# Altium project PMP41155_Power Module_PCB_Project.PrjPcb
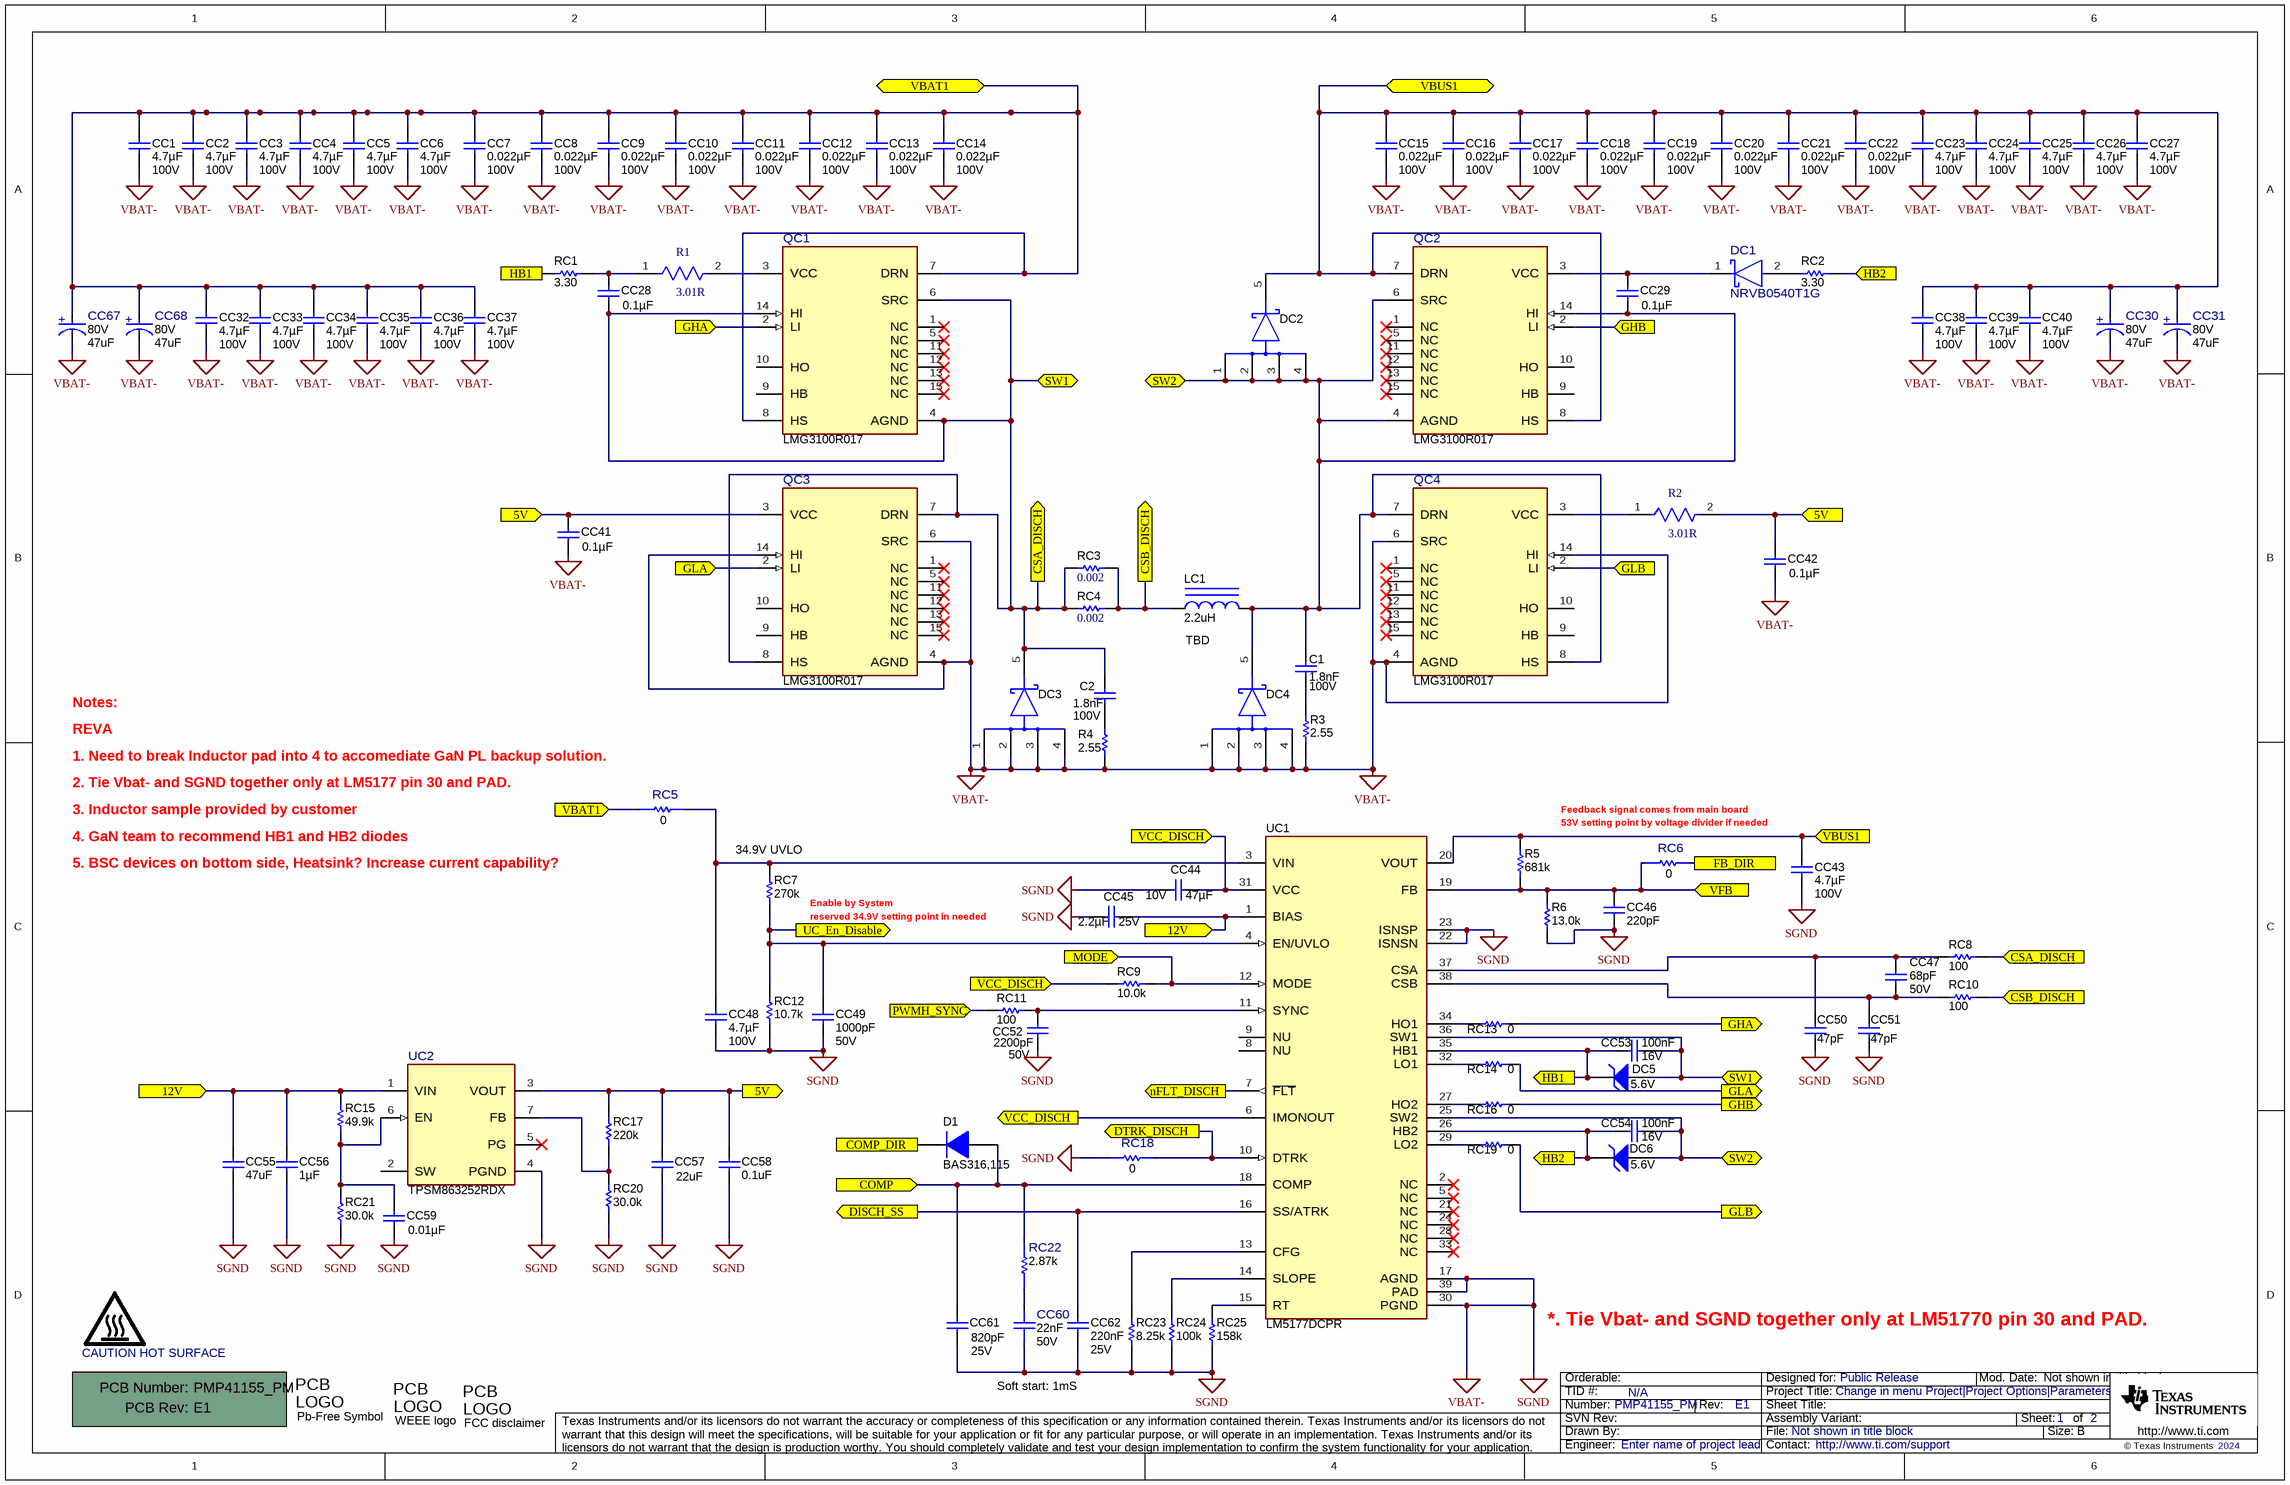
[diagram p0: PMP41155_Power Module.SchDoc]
CopyrightYear: 2024; PCB_Layout: Richard Yin; PCB_Rev: E1; PRJ_Customer: Public Release; PRJ_Engineer: Enter name of project lead; PRJ_Number: PMP41155_PM; PRJ_Title: Change in menu Project|Project Options|Parameters; SCH_Rev: E1; TechSupport: http://www.ti.com/support; TID: N/A
2 sheets, 131 parts. Net scope: flat (ports and power ports of the same name join across sheets).
Board file: PMP41155_Power Module.PcbDoc
Sheets:
  PMP41155_Power Module.SchDoc
  PMP41155_Power Module_1.SchDoc

## Sheet PMP41155_Power Module.SchDoc
size 431 x 279 mm; Date: Not shown in title block; ApprovedBy: Not shown in title block; CheckedBy: Not shown in title block; Author: Not shown in title block; CompanyName: Not shown in title block; Engineer: Not shown in title block; Organization: Not shown in title block; Address1: Not shown in title block; Address2: Not shown in title block; Address3: Not shown in title block; Address4: Not shown in title block; DocumentNumber: 1; Revision: Use project parameter SCH_Rev; SheetNumber: 1; SheetTotal: 2; PageSetup: Record=PageOptions¦CenterHorizontal=True¦CenterVertical=True¦PrintScale=1.00¦XCorrection=1.00¦YCorrection=1.00¦PrintKind=0¦BorderSize=5000000¦LeftOffset=0¦BottomOffset=0¦Orientation=2¦PaperLength=1000¦PaperWidth=1000¦Scale=100¦PaperSource=15¦PrintQuality=600¦MediaType=1¦DitherType=10¦PaperKind=Letter¦PrintScaleMode=1

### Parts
!PCB1  Printed Circuit Board  (value not drawn)  (mechanical)
C1  Cap_F: 1.8nF  VDC_V: 100V  [0603]  (hidden comment: GRM188R72A182KA01D)
C2  Cap_F: 1.8nF  VDC_V: 100V  [0603]  (hidden comment: GRM188R72A182KA01D)
CC1  ValueDisplayed: 4.7µF  Value2: 100V  [1206_180]  (hidden comment: GRJ31CC72A475KE01L)
CC2  ValueDisplayed: 4.7µF  Value2: 100V  [1206_180]  (hidden comment: GRJ31CC72A475KE01L)
CC3  ValueDisplayed: 4.7µF  Value2: 100V  [1206_180]  (hidden comment: GRJ31CC72A475KE01L)
CC4  ValueDisplayed: 4.7µF  Value2: 100V  [1206_180]  (hidden comment: GRJ31CC72A475KE01L)
CC5  ValueDisplayed: 4.7µF  Value2: 100V  [1206_180]  (hidden comment: GRJ31CC72A475KE01L)
CC6  ValueDisplayed: 4.7µF  Value2: 100V  [1206_180]  (hidden comment: GRJ31CC72A475KE01L)
CC7  ValueDisplayed: 0.022µF  Value2: 100V  [0603]  (hidden comment: CGA3E2X7R2A223K080AA)
CC8  ValueDisplayed: 0.022µF  Value2: 100V  [0603]  (hidden comment: CGA3E2X7R2A223K080AA)
CC9  ValueDisplayed: 0.022µF  Value2: 100V  [0603]  (hidden comment: CGA3E2X7R2A223K080AA)
CC10  ValueDisplayed: 0.022µF  Value2: 100V  [0603]  (hidden comment: CGA3E2X7R2A223K080AA)
CC11  ValueDisplayed: 0.022µF  Value2: 100V  [0603]  (hidden comment: CGA3E2X7R2A223K080AA)
CC12  ValueDisplayed: 0.022µF  Value2: 100V  [0603]  (hidden comment: CGA3E2X7R2A223K080AA)
CC13  ValueDisplayed: 0.022µF  Value2: 100V  [0603]  (hidden comment: CGA3E2X7R2A223K080AA)
CC14  ValueDisplayed: 0.022µF  Value2: 100V  [0603]  (hidden comment: CGA3E2X7R2A223K080AA)
CC15  ValueDisplayed: 0.022µF  Value2: 100V  [0603]  (hidden comment: CGA3E2X7R2A223K080AA)
CC16  ValueDisplayed: 0.022µF  Value2: 100V  [0603]  (hidden comment: CGA3E2X7R2A223K080AA)
CC17  ValueDisplayed: 0.022µF  Value2: 100V  [0603]  (hidden comment: CGA3E2X7R2A223K080AA)
CC18  ValueDisplayed: 0.022µF  Value2: 100V  [0603]  (hidden comment: CGA3E2X7R2A223K080AA)
CC19  ValueDisplayed: 0.022µF  Value2: 100V  [0603]  (hidden comment: CGA3E2X7R2A223K080AA)
CC20  ValueDisplayed: 0.022µF  Value2: 100V  [0603]  (hidden comment: CGA3E2X7R2A223K080AA)
CC21  ValueDisplayed: 0.022µF  Value2: 100V  [0603]  (hidden comment: CGA3E2X7R2A223K080AA)
CC22  ValueDisplayed: 0.022µF  Value2: 100V  [0603]  (hidden comment: CGA3E2X7R2A223K080AA)
CC23  ValueDisplayed: 4.7µF  Value2: 100V  [1206_180]  (hidden comment: GRJ31CC72A475KE01L)
CC24  ValueDisplayed: 4.7µF  Value2: 100V  [1206_180]  (hidden comment: GRJ31CC72A475KE01L)
CC25  ValueDisplayed: 4.7µF  Value2: 100V  [1206_180]  (hidden comment: GRJ31CC72A475KE01L)
CC26  ValueDisplayed: 4.7µF  Value2: 100V  [1206_180]  (hidden comment: GRJ31CC72A475KE01L)
CC27  ValueDisplayed: 4.7µF  Value2: 100V  [1206_180]  (hidden comment: GRJ31CC72A475KE01L)
CC28  ValueDisplayed: 0.1µF  [0402]  (hidden comment: GCM155R71C104JA55D)
CC29  ValueDisplayed: 0.1µF  [0402]  (hidden comment: GCM155R71C104JA55D)
CC30  VDC_V: 80V  ValueDisplayed: 47uF  [FP-865081757008_SMT_CAP_10MM3_10MM3-MFG]  (hidden comment: 865081757008)
CC31  VDC_V: 80V  ValueDisplayed: 47uF  [FP-865081757008_SMT_CAP_10MM3_10MM3-MFG]  (hidden comment: 865081757008)
CC32  ValueDisplayed: 4.7µF  Value2: 100V  [1206_180]  (hidden comment: GRJ31CC72A475KE01L)
CC33  ValueDisplayed: 4.7µF  Value2: 100V  [1206_180]  (hidden comment: GRJ31CC72A475KE01L)
CC34  ValueDisplayed: 4.7µF  Value2: 100V  [1206_180]  (hidden comment: GRJ31CC72A475KE01L)
CC35  ValueDisplayed: 4.7µF  Value2: 100V  [1206_180]  (hidden comment: GRJ31CC72A475KE01L)
CC36  ValueDisplayed: 4.7µF  Value2: 100V  [1206_180]  (hidden comment: GRJ31CC72A475KE01L)
CC37  ValueDisplayed: 4.7µF  Value2: 100V  [1206_180]  (hidden comment: GRJ31CC72A475KE01L)
CC38  ValueDisplayed: 4.7µF  Value2: 100V  [1206_180]  (hidden comment: GRJ31CC72A475KE01L)
CC39  ValueDisplayed: 4.7µF  Value2: 100V  [1206_180]  (hidden comment: GRJ31CC72A475KE01L)
CC40  ValueDisplayed: 4.7µF  Value2: 100V  [1206_180]  (hidden comment: GRJ31CC72A475KE01L)
CC41  ValueDisplayed: 0.1µF  [0402]  (hidden comment: GCM155R71C104JA55D)
CC42  ValueDisplayed: 0.1µF  [0402]  (hidden comment: GCM155R71C104JA55D)
CC43  ValueDisplayed: 4.7µF  Value2: 100V  [1206_180]  (hidden comment: GRJ31CC72A475KE01L)
CC44  VDC_V: 10V  ValueDisplayed: 47µF  [0805_HV]  (hidden comment: GRM21BR61A476ME15L)
CC45  ValueDisplayed: 2.2µF  Value2: 25V  [0805_HV]  (hidden comment: GRM219R61E225KA12D)
CC46  ValueDisplayed: 220pF  [0603]  (hidden comment: GRM188R71H221KA01D)
CC47  ValueDisplayed: 68pF  Value2: 50V  [0603]  (hidden comment: 06035A680JAT2A)
CC48  ValueDisplayed: 4.7µF  Value2: 100V  [1206_180]  (hidden comment: GRJ31CC72A475KE01L)
CC49  ValueDisplayed: 1000pF  Value2: 50V  [0603]  (hidden comment: GRM1885C1H102JA01D)
CC50  ValueDisplayed: 47pF  [0603]  (hidden comment: C0603C470J5GACTU)
CC51  ValueDisplayed: 47pF  [0603]  (hidden comment: C0603C470J5GACTU)
CC52  ValueDisplayed: 2200pF  Value2: 50V  [0603]  (hidden comment: GRM188R61H222KA01D)
CC53  Cap_F: 100nF  VDC_V: 16V  [0603]  (hidden comment: GCM188R71C104KA37J)
CC54  Cap_F: 100nF  VDC_V: 16V  [0603]  (hidden comment: GCM188R71C104KA37J)
CC55  ValueDisplayed: 47uF  [1210_270]  (hidden comment: GRM32ER61C476KE15L)
CC56  Cap_F: 1µF  [0805_HV]  (hidden comment: C0805C105K3RACTU)
CC57  ValueDisplayed: 22uF  [0805_HV]  (hidden comment: CL21A226KQQNNNE)
CC58  ValueDisplayed: 0.1uF  [0402]  (hidden comment: GRM155R70J104KA01D)
CC59  ValueDisplayed: 0.01µF  [0402]  (hidden comment: C0402C103K4RACTU)
CC60  Cap_F: 22nF  VDC_V: 50V  [FP-CL10B223KB8NNNC_0603-IPC_C]  (hidden comment: CL10B223KB8NNNC)
CC61  VDC_V: 25V  ValueDisplayed: 820pF  [0603]  (hidden comment: GRM1885C1E821JA01D)
CC62  Cap_F: 220nF  VDC_V: 25V  [0805_HV]  (hidden comment: 08053C224MAT2A)
CC67  VDC_V: 80V  ValueDisplayed: 47uF  [FP-865081757008_SMT_CAP_10MM3_10MM3-MFG]  (hidden comment: 865081757008)
CC68  VDC_V: 80V  ValueDisplayed: 47uF  [FP-865081757008_SMT_CAP_10MM3_10MM3-MFG]  (hidden comment: 865081757008)
D1  BAS316,115  [SOD-323]
DC1  NRVB0540T1G  [FP-NRVB0540T1G_SOD-123-MFG]
DC2  STPS30M100DJF-TR  [FP-STPS30M100DJF-TR_PowerFlat6-MFG]  (value not drawn)
DC3  STPS30M100DJF-TR  [FP-STPS30M100DJF-TR_PowerFlat6-MFG]  (value not drawn)
DC4  STPS30M100DJF-TR  [FP-STPS30M100DJF-TR_PowerFlat6-MFG]  (value not drawn)
DC5  value 5.6V  [SOD-123]  (hidden comment: MMSZ4690-E3-08)
DC6  value 5.6V  [SOD-123]  (hidden comment: MMSZ4690-E3-08)
LC1  TBD  ValueDisplayed: 2.2uH  [WE-HCB_1890]
LOGO1  CAUTION HOT SURFACE  [IEC_HotSurface_Small]  (no BOM)
Logo2  Pb-Free Symbol  [Pb-Free_Overlay_Medium]  (no BOM)
Logo3  WEEE logo  [WEEE_Minimum]  (no BOM)
Logo4  FCC disclaimer  [FCC_disclaimer]  (no BOM)
QC1  LMG3100R017  [VBE0015A-MFG]
QC2  LMG3100R017  [VBE0015A-MFG]
QC3  LMG3100R017  [VBE0015A-MFG]
QC4  LMG3100R017  [VBE0015A-MFG]
R1  Resistance: 3.01R  [FP-CRCW0402-e3-MFG]  (hidden comment: CRCW04023R01FNED)
R2  Resistance: 3.01R  [FP-CRCW0402-e3-MFG]  (hidden comment: CRCW04023R01FNED)
R3  ValueDisplayed: 2.55  [1206]  (hidden comment: CRCW12062R55FKEA)
R4  ValueDisplayed: 2.55  [1206]  (hidden comment: CRCW12062R55FKEA)
R5  ValueDisplayed: 681k  [0603]  (hidden comment: CRCW0603681KFKEA)
R6  ValueDisplayed: 13.0k  [0603]  (hidden comment: CRCW060313K0FKEA)
RC1  ValueDisplayed: 3.30  [1206]  (hidden comment: RC1206FR-073R3L)
RC2  ValueDisplayed: 3.30  [1206]  (hidden comment: RC1206FR-073R3L)
RC3  ValueDisplayed: 0.002  [0508]  (hidden comment: KRL2012E-M-R002-G-T5)
RC4  ValueDisplayed: 0.002  [0508]  (hidden comment: KRL2012E-M-R002-G-T5)
RC5  Res_ohm: 0  [FP-JR0805X35E_0805-MFG]  (hidden comment: JR0805X35E)
RC6  Res_ohm: 0  [FP-JR0805X35E_0805-MFG]  (hidden comment: JR0805X35E)
RC7  ValueDisplayed: 270k  [0603]  (hidden comment: CRCW0603270KJNEA)
RC8  ValueDisplayed: 100  [0603]  (hidden comment: RC0603FR-07100RL)
RC9  ValueDisplayed: 10.0k  [0603]  (hidden comment: CRCW060310K0FKEA)
RC10  ValueDisplayed: 100  [0603]  (hidden comment: RC0603FR-07100RL)
RC11  ValueDisplayed: 100  [0603]  (hidden comment: CRCW0603100RFKEA)
RC12  ValueDisplayed: 10.7k  [0603]  (hidden comment: CRCW060310K7FKEA)
RC13  ValueDisplayed: 0  [0603]  (hidden comment: CRCW06030000Z0EA)
RC14  ValueDisplayed: 0  [0603]  (hidden comment: CRCW06030000Z0EA)
RC15  ValueDisplayed: 49.9k  [0402]  (hidden comment: CRCW040249K9FKED)
RC16  ValueDisplayed: 0  [0603]  (hidden comment: CRCW06030000Z0EA)
RC17  ValueDisplayed: 220k  [0402]  (hidden comment: RC0402FR-07220KL)
RC18  Res_ohm: 0  [FP-JR0805X35E_0805-MFG]  (hidden comment: JR0805X35E)
RC19  ValueDisplayed: 0  [0603]  (hidden comment: CRCW06030000Z0EA)
RC20  ValueDisplayed: 30.0k  [0402]  (hidden comment: CRCW040230K0FKED)
RC21  ValueDisplayed: 30.0k  [0402]  (hidden comment: CRCW040230K0FKED)
RC22  Res_ohm: 2.87k  [FP-RK73H1ETTP2871F_0402-MFG]  (hidden comment: RK73H1ETTP2871F)
RC23  ValueDisplayed: 8.25k  [0603]  (hidden comment: CRCW06038K25FKEA)
RC24  ValueDisplayed: 100k  [0603]  (hidden comment: CRCW0603100KFKEA)
RC25  ValueDisplayed: 158k  [0603]  (hidden comment: CRCW0603158KFKEA)
UC1  LM5177DCPR  [DCP0038A-MFG]
UC2  TPSM863252RDX  [RDX0007A-MFG]

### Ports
5V (in), 5V (out), 12V (in), COMP (in), COMP_DIR (out), CSA_DISCH (in), CSA_DISCH (out), CSB_DISCH (in), CSB_DISCH (out), DISCH_SS (out), DTRK_DISCH (out), FB_DIR (in), GHA (in), GHA (out), GHB (in), GHB (out), GLA (in), GLA (out), GLB (in), GLB (out), HB1 (in), HB1 (out), HB2 (in), HB2 (out), MODE (in), nFLT_DISCH (out), PWMH_SYNC (in), SW1 (bidir), SW2 (bidir), UC_En_Disable (out), VBAT1 (bidir), VBAT1 (in), VBUS1 (bidir), VBUS1 (in), VCC_DISCH (in), VCC_DISCH (out), VFB (in)

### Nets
SGND: CC1.2 CC2.2 CC3.2 CC4.2 CC5.2 CC6.2 CC7.2 CC8.2 CC9.2 CC10.2 CC11.2 CC12.2 CC13.2 CC14.2 CC15.2 CC16.2 CC17.2 CC18.2 CC19.2 CC20.2 CC21.2 CC22.2 CC23.2 CC24.2 CC25.2 CC26.2 CC27.2 CC30.1(CATHODE) CC31.1(CATHODE) CC32.2 CC33.2 CC34.2 CC35.2 CC36.2 CC37.2 CC38.2 CC39.2 CC40.2 CC41.2 CC42.2 CC43.2 CC44.2 CC45.1 CC46.2 CC48.2 CC49.2 CC50.2 CC51.2 CC52.1 CC55.2 CC56.2 CC57.2 CC58.2 CC59.2 CC60.1 CC61.2 CC62.2 CC67.1(CATHODE) CC68.1(CATHODE) DC3.1(A) DC3.2(A) DC3.3(A) DC3.4(A) DC4.1(A) DC4.2(A) DC4.3(A) DC4.4(A) QC3.4(AGND) QC3.6(SRC) QC3.14(HI) QC4.4(AGND) QC4.6(SRC) QC4.14(HI) R3.1 R4.1 R6.1 RC12.1 RC18.1 RC20.1 RC21.1 RC23.1 RC24.1 RC25.1 UC1.17(AGND) UC1.22(ISNSN) UC1.23(ISNSP) UC1.30(PGND) UC1.39(PAD) UC2.4(PGND)  [also labelled VBAT-]
5V: CC41.1 CC42.1 CC57.1 CC58.1 QC3.3(VCC) R2.2 RC17.2 UC2.3(VOUT) ; port 5V
12V: CC45.2 CC55.1 CC56.1 RC15.2 UC1.1(BIAS) UC2.1(VIN) ; port 12V
COMP: CC61.1 D1.2(A) RC22.2 UC1.18(COMP) ; port COMP
COMP_DIR: D1.1(K) ; port COMP_DIR
CSA_DISCH: C2.1 CC28.2 CC53.1 DC3.5(K) DC5.2(A) QC1.4(AGND) QC1.6(SRC) QC1.14(HI) QC3.7(DRN) QC3.8(HS) RC3.1 RC4.1 RC8.2 UC1.36(SW1) ; port CSA_DISCH, port SW1
CSB_DISCH: LC1.1 RC3.2 RC4.2 RC10.2 ; port CSB_DISCH
DISCH_SS: CC62.1 UC1.16(SS/ATRK) ; port DISCH_SS
DTRK_DISCH: RC18.2 UC1.10(DTRK) ; port DTRK_DISCH
FB_DIR: RC6.2 ; port FB_DIR
GHA: QC1.2(LI) RC13.2 ; port GHA
GHB: QC2.2(LI) RC16.2 ; port GHB
GLA: QC3.2(LI) RC14.2 ; port GLA
GLB: QC4.2(LI) RC19.2 ; port GLB
HB1: CC53.2 DC5.1(K) RC1.1 UC1.35(HB1) ; port HB1
HB2: CC54.2 DC6.1(K) RC2.2 UC1.26(HB2) ; port HB2
MODE: RC9.2 UC1.12(MODE) ; port MODE
nFLT_DISCH: UC1.7(~{FLT}) ; port nFLT_DISCH
PWMH_SYNC: RC11.1 ; port PWMH_SYNC
SW2: C1.1 CC29.2 CC54.1 DC2.1(A) DC2.2(A) DC2.3(A) DC2.4(A) DC4.5(K) DC6.2(A) LC1.2 QC2.4(AGND) QC2.6(SRC) QC2.14(HI) QC4.7(DRN) QC4.8(HS) UC1.25(SW2) ; port SW2
UC_En_Disable: CC49.1 RC7.1 RC12.2 UC1.4(EN/UVLO) ; port UC_En_Disable
VBAT1: CC1.1 CC2.1 CC3.1 CC4.1 CC5.1 CC6.1 CC7.1 CC8.1 CC9.1 CC10.1 CC11.1 CC12.1 CC13.1 CC14.1 CC32.1 CC33.1 CC34.1 CC35.1 CC36.1 CC37.1 CC67.2(ANODE) CC68.2(ANODE) QC1.7(DRN) QC1.8(HS) RC5.1 ; port VBAT1
VBUS1: CC15.1 CC16.1 CC17.1 CC18.1 CC19.1 CC20.1 CC21.1 CC22.1 CC23.1 CC24.1 CC25.1 CC26.1 CC27.1 CC30.2(ANODE) CC31.2(ANODE) CC38.1 CC39.1 CC40.1 CC43.1 DC2.5(K) QC2.7(DRN) QC2.8(HS) R5.2 UC1.20(VOUT) ; port VBUS1
VCC_DISCH: CC44.1 RC9.1 UC1.6(IMONOUT) UC1.31(VCC) ; port VCC_DISCH
VFB: CC46.1 R5.1 R6.2 RC6.1 UC1.19(FB) ; port VFB
NetC1_2: C1.2 R3.2
NetC2_2: C2.2 R4.2
NetCC28_1: CC28.1 R1.1 RC1.2
NetCC29_1: CC29.1 DC1.1(CATHODE) QC2.3(VCC)
NetCC47_1: CC47.1 CC50.1 RC8.1 UC1.37(CSA)
NetCC47_2: CC47.2 CC51.1 RC10.1 UC1.38(CSB)
NetCC48_1: CC48.1 RC5.2 RC7.2 UC1.3(VIN)
NetCC52_2: CC52.2 RC11.2 UC1.11(SYNC)
NetCC59_1: CC59.1 RC15.1 RC21.2 UC2.6(EN)
NetCC60_2: CC60.2 RC22.1
NetDC1_2: DC1.2(ANODE) RC2.1
NetQC1_3: QC1.3(VCC) R1.2
NetQC4_3: QC4.3(VCC) R2.1
NetRC13_1: RC13.1 UC1.34(HO1)
NetRC14_1: RC14.1 UC1.32(LO1)
NetRC16_1: RC16.1 UC1.27(HO2)
NetRC17_1: RC17.1 RC20.2 UC2.7(FB)
NetRC19_1: RC19.1 UC1.29(LO2)
NetRC23_2: RC23.2 UC1.13(CFG)
NetRC24_2: RC24.2 UC1.14(SLOPE)
NetRC25_2: RC25.2 UC1.15(RT)

Not connected (* = marked no-connect by the designer): QC1 1(NC)* 5(NC)* 9(HB) 10(HO) 11(NC)* 12(NC)* 13(NC)* 15(NC)*; QC2 1(NC)* 5(NC)* 9(HB) 10(HO) 11(NC)* 12(NC)* 13(NC)* 15(NC)*; QC3 1(NC)* 5(NC)* 9(HB) 10(HO) 11(NC)* 12(NC)* 13(NC)* 15(NC)*; QC4 1(NC)* 5(NC)* 9(HB) 10(HO) 11(NC)* 12(NC)* 13(NC)* 15(NC)*; UC1 2(NC)* 5(NC)* 8(NU) 9(NU) 21(NC)* 24(NC)* 28(NC)* 33(NC)*; UC2 2(SW) 5(PG)*

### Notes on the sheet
- Notes:
- (near RC5) 1. Need to break Inductor pad into 4 to accomediate GaN PL backup solution.
- REVA
- 2. Tie Vbat- and SGND together only at LM5177 pin 30 and PAD.
- 3. Inductor sample provided by customer
- 4. GaN team to recommend HB1 and HB2 diodes
- Feedback signal comes from main board
- 53V setting point by voltage divider if needed
- 5. BSC devices on bottom side, Heatsink? Increase current capability?
- (near RC7) 34.9V UVLO
- (near RC7) Enable by System
- (near RC7) reserved 34.9V setting point in needed
- *. Tie Vbat- and SGND together only at LM51770 pin 30 and PAD.
- Soft start: 1mS

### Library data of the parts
!PCB1 = CMP-0003618-2: Manufacturer: Any; PartNumber: PMP41155_PM
C1 C2 = CMP-0007473-4: CAP, CERM, 1800 pF, 100 V, +/- 10%, X7R, 0603; Manufacturer: MuRata; TaMin_C: -55°C; Polarized: N; SizeAreaWB_mm2: 4.68; Value1: Unknown; U/M: EA; Value: 1800pF; TaMax_C: 125°C; SizeZ_mm: 1; SizeX_mm: 1.6; SizeY_mm: 0.8; SizeArea_mm2: 1.28; AEC Category: Q200
CC1-CC6 CC23-CC27 CC32-CC40 CC43 CC48 = C3216X6S1H475K160AB: CAP CER 4.7UF 100V X7S 1206; Polarized: N; CompType: Capacitor; U/M: EA; Cap_F: 0.0000047; Tolerance_%: 10; VDC_V: 100; TaMin_C: -55; TaMax_C: 105; Cap_Case: 1206; SizeArea_mm2: 5.12; SizeAreaWB_mm2: 10.92; SizeX_mm: 3.2; SizeY_mm: 1.6; SizeZ_mm: 1.8; AEC Category: Q200
CC7-CC22 = CGA3E2X7R2A223K080AA: CAP, CERM, 0.022 µF, 100 V,+/- 10%, X7R, AEC-Q200 Grade 1, 0603; Manufacturer: TDK; Polarized: N; CompType: Capacitor; Value: 0.022uF; U/M: EA; Cap_F: 0.000000022; Tolerance_%: 10; ESR_ohm: 0.083542; Value1: 0.083542 ohm; VDC_V: 100; IRMS_A: 0.609312; TaMin_C: -55; TaMax_C: 125; SizeArea_mm2: 1.28; SizeAreaWB_mm2: 4.68; SizeX_mm: 1.6; SizeY_mm: 0.8; SizeZ_mm: 1; AEC Category: Q200; AEC Qualified: Y
CC28 CC29 CC41 CC42 = CMP-0080702-1: CAP, CERM, 0.1 µF, 16 V,+/- 5%, X7R, AEC-Q200 Grade 1, 0402; Manufacturer: MuRata; Cap_F: 100nF; SizeAreaWB_mm2: 3; SizeArea_mm2: 0.5; AEC Qualified: Y; AEC Category: Q200; Value: 0.1uF; TaMax_C: 125°C; SizeZ_mm: 0.6; AEC Grade: 1; Polarized: N; TaMin_C: -55°C; VDC_V: 16V; U/M: EA
CC30 CC31 CC67 CC68 = CMP-0095714-1: Aluminum Electrolytic Capacitor 47uF 20% 80V 10.3x10.3x10.5mm SMT; Manufacturer: Wurth Electronics; IRMS_A: 160mA; SizeZ_mm: 10.5mm; Life: 2000Hours; AEC Qualified: No; Leakage Current: 37.6uA; Dissipation Factor: 10%; Value: 47µF
CC44 = CMP-0078699-1: CAP, CERM, 47 µF, 10 V,+/- 20%, X5R, 0805; Manufacturer: MuRata; TaMin_C: -55°C; Polarized: N; Green_Lifecycle: Active; SizeAreaWB_mm2: 6.75; Green_REACh: Passed; U/M: EA; Value: 47uF; TaMax_C: 85°C; SizeZ_mm: 1.45; SizeX_mm: 2; SizeY_mm: 1.25; Cap_Case: 0805; SizeArea_mm2: 2.5; AEC Category: Q200
CC45 = GRM219R61E225KA12D: CAP, CERM, 2.2 µF, 25 V,+/- 10%, X5R, 0805; Manufacturer: MuRata; Polarized: N; CompType: Capacitor; Value: 2.2uF; U/M: EA; Cap_F: 0.0000022; Tolerance_%: 10; ESR_ohm: 0.006; Value1: 0.006 ohm; VDC_V: 25; TaMin_C: -55; TaMax_C: 85; Cap_Case: 0805; SizeArea_mm2: 2.5; SizeAreaWB_mm2: 6.75; SizeX_mm: 2; SizeY_mm: 1.25; SizeZ_mm: 1.45; AEC Category: Q200; Green_Lifecycle: Active; Green_REACh: Passed
CC46 = GRM188R71H221KA01D: CAP, CERM, 220 pF, 50 V,+/- 10%, X7R, 0603; Manufacturer: MuRata; Polarized: N; CompType: Capacitor; Value: 220pF; U/M: EA; Cap_F: 0.00000000022; Tolerance_%: 10; VDC_V: 50; Value2: 50V; TaMin_C: -55; TaMax_C: 125; SizeArea_mm2: 1.28; SizeAreaWB_mm2: 4.68; SizeX_mm: 1.6; SizeY_mm: 0.8; SizeZ_mm: 1; AEC Category: Q200; Green_Lifecycle: Active; Green_REACh: Passed
CC47 = 06035A680JAT2A: CAP, CERM, 68 pF, 50 V,+/- 5%, C0G/NP0, 0603; Manufacturer: AVX; Polarized: N; CompType: Capacitor; Value: 68pF; U/M: EA; Cap_F: 0.000000000068; Tolerance_%: 5; ESR_ohm: 0.144; Value1: 0.144 ohm; VDC_V: 50; TaMin_C: -55; TaMax_C: 125; SizeArea_mm2: 1.28; SizeAreaWB_mm2: 4.68; SizeX_mm: 1.6; SizeY_mm: 0.8; SizeZ_mm: 1; AEC Category: Q200; Green_Lifecycle: Active; Green_REACh: Passed
CC49 = GRM1885C1H102JA01D: CAP, CERM, 1000 pF, 50 V,+/- 5%, C0G/NP0, 0603; Manufacturer: MuRata; Polarized: N; CompType: Capacitor; Value: 1000pF; U/M: EA; Cap_F: 0.000000001; Tolerance_%: 5; VDC_V: 50; TaMin_C: -55; TaMax_C: 125; SizeArea_mm2: 1.28; SizeAreaWB_mm2: 4.68; SizeX_mm: 1.6; SizeY_mm: 0.8; SizeZ_mm: 1; AEC Category: Q200; Green_Lifecycle: Active; Green_REACh: Passed
CC50 CC51 = CMP-0006939-4: CAP, CERM, 47 pF, 50 V, +/- 5%, C0G/NP0, 0603; Manufacturer: Kemet; TaMin_C: -55°C; Polarized: N; SizeAreaWB_mm2: 4.68; Value1: Unknown; U/M: EA; Value: 47pF; TaMax_C: 125°C; SizeZ_mm: 1; SizeX_mm: 1.6; SizeY_mm: 0.8; Value2: 50V; SizeArea_mm2: 1.28; AEC Category: Q200
CC52 = GRM188R61H222KA01D: CAP, CERM, 2200 pF, 50 V,+/- 10%, X5R, 0603; Manufacturer: MuRata; Polarized: N; CompType: Capacitor; Value: 2200pF; U/M: EA; Cap_F: 0.0000000022; Tolerance_%: 10; VDC_V: 50; TaMin_C: -55; TaMax_C: 85; SizeArea_mm2: 1.28; SizeAreaWB_mm2: 4.68; SizeX_mm: 1.6; SizeY_mm: 0.8; SizeZ_mm: 1; AEC Category: Q200
CC53 CC54 = CMP-0007135-4: CAP, CERM, 0.1 uF, 16 V, +/- 10%, X7R, AEC-Q200 Grade 1, 0603; Manufacturer: MuRata; TaMin_C: -55°C; Polarized: N; SizeAreaWB_mm2: 4.68; Value1: Unknown; U/M: EA; Value: 0.1uF; TaMax_C: 125°C; SizeZ_mm: 1; SizeX_mm: 1.6; SizeY_mm: 0.8; SizeArea_mm2: 1.28; AEC Qualified: Y; AEC Category: Q200
CC55 = CMP-0009211-1: CAP, CERM, 47 uF, 16 V, +/- 10%, X5R, 1210; Manufacturer: MuRata; TaMin_C: -55°C; Polarized: N; SizeAreaWB_mm2: 14.7; Value1: Unknown; U/M: EA; Value: 47uF; TaMax_C: 85°C; SizeZ_mm: 2.7; SizeX_mm: 3.2; SizeY_mm: 2.5; Cap_Case: 1210; Value2: 16V; SizeArea_mm2: 8; CompType: Capacitor; Cap_F: 47µF; AEC Category: Q200
CC56 = CMP-0007728-2: CAP, CERM, 1 uF, 25 V, +/- 10%, X7R, 0805; Manufacturer: Kemet; TaMin_C: -55°C; Polarized: N; SizeAreaWB_mm2: 6.75; Value1: Unknown; U/M: EA; Value: 1uF; TaMax_C: 125°C; SizeZ_mm: 1.45; SizeX_mm: 2; SizeY_mm: 1.25; Cap_Case: 0805; Value2: 25V; SizeArea_mm2: 2.5; CompType: Capacitor; AEC Category: Q200
CC57 = CMP-0007989-2: CAP, CERM, 22 uF, 6.3 V, +/- 10%, X5R, 0805; Manufacturer: Samsung Electro-Mechanics; TaMin_C: -55°C; Polarized: N; SizeAreaWB_mm2: 6.75; Value1: Unknown; U/M: EA; Value: 22uF; TaMax_C: 85°C; SizeZ_mm: 1.45; SizeX_mm: 2; SizeY_mm: 1.25; Cap_Case: 0805; Value2: 6.3V; SizeArea_mm2: 2.5; CompType: Capacitor; Cap_F: 22µF; AEC Category: Q200
CC58 = GRM155R70J104KA01D: CAP, CERM, 0.1uF, 6.3V, +/-10%, X7R, 0402; Manufacturer: MuRata; Polarized: N; CompType: Capacitor; U/M: EA; Cap_F: 0.0000001; Tolerance_%: 10; Value1: Unknown; VDC_V: 6.3; TaMin_C: -55; TaMax_C: 125
CC59 = CMP-0078218-1: CAP, CERM, 0.01 µF, 16 V,+/- 10%, X7R, 0402; Manufacturer: Kemet; TaMin_C: -55°C; Polarized: N; Green_Lifecycle: Active; SizeAreaWB_mm2: 3; Green_REACh: Passed; U/M: EA; Value: 0.01uF; TaMax_C: 125°C; SizeZ_mm: 0.6; SizeX_mm: 1; SizeY_mm: 0.5; Value2: 16V; CompType: Capacitor; Cap_F: 10nF; AEC Category: Q200
CC60 = CMP-0095696-1: Cap Ceramic 22nF 50V X7R ±10% Pad SMD 0603 +125°C T/R; Manufacturer: Samsung; TempCo: 0.15; SizeZ_mm: 0.9mm; AEC Qualified: No
CC61 = CMP-0007168-4: CAP, CERM, 820 pF, 25 V, +/- 5%, C0G/NP0, 0603; Manufacturer: MuRata; TaMin_C: -55°C; Polarized: N; SizeAreaWB_mm2: 4.68; Value1: Unknown; U/M: EA; Value: 820pF; TaMax_C: 125°C; SizeZ_mm: 1; SizeX_mm: 1.6; SizeY_mm: 0.8; SizeArea_mm2: 1.28; AEC Category: Q200
CC62 = CMP-0007572-2: CAP, CERM, 0.22 uF, 25 V, +/- 20%, X7R, 0805; Manufacturer: AVX; TaMin_C: -55°C; ESR_ohm: 16m; Polarized: N; SizeAreaWB_mm2: 6.75; Value1: 0.016 ohm; U/M: EA; Value: 0.22uF; TaMax_C: 125°C; SizeZ_mm: 1.45; SizeX_mm: 2; SizeY_mm: 1.25; Cap_Case: 0805; SizeArea_mm2: 2.5; AEC Category: Q200
D1 = CMP-0029006-2: Diode, Ultrafast, 100 V, 0.25 A, SOD-323; Manufacturer: Nexperia; SizeY_mm: 1.35; Value1: 0.25A; SizeAreaWB_mm2: 8.695; SizeZ_mm: 1; Io_A: 250mA; Value2: 1.4V; SizeX_mm: 2.7; Green_REACh: Incomplete; TJmax_C: 150°C; Green_Lifecycle: Not Set; Vr_V: 100V; AEC Category: Q101; Value: 100V; SizeArea_mm2: 3.645
DC1 = CMP-0090564-1: Diode Schottky 40V 500mA Surface Mount SOD-123; Manufacturer: On Semiconductor; Max Surge Forward Current: 5.5A; Standoff Height: 0mm; Import Ts: 1521847448; AEC Grade: Grade 0; AEC Qualified: Yes; Peak Reverse Current: 20uA; SizeZ_mm: 1.35mm; TJmax_C: 150°C; Ciiva Ids: 822523; Forward Current: 0.5A
DC2-DC4 = CMP-0032275-1: Diode 100 V 30A Surface Mount PowerFlat™ (5x6); Manufacturer: STMicroelectronics; AEC Qualified: No; SizeZ_mm: 1.05mm; TJmax_C: 150°C; Vf_V: 100V; Max Surge Forward Current: 200A; Peak Reverse Current: 100uA; Standoff Height: 0mm
DC5 DC6 = CMP-0077600-3: Diode, Zener, 5.6 V, 500 mW, SOD-123; Manufacturer: Vishay-Semiconductor; RJA_CperW: 340; SizeArea_mm2: 6.545; SizeAreaWB_mm2: 13.095; Value1: 0.5W; SizeZ_mm: 1.35; AEC Category: Q101; AEC Qualified: N; SizeX_mm: 3.85; SizeY_mm: 1.7; Power_W: 500mW
LC1 = CMP-0064042-1: Green_Lifecycle: Active; SizeAreaWB_mm2: 410.06; DCR_ohm: 1.6m; Green_REACh: Passed; SizeZ_mm: 9.2; SizeX_mm: 18.3; SizeY_mm: 18.2; SizeArea_mm2: 333.06; CompType: Inductor; Ind_H: 2.2µH; AEC Category: Q200
LOGO1 = CMP-0074837-1: IEC 61010-1 Hot Surface Warning; Library Reference: IEC_HotSurface; SymbolCreator: a0412235
Logo2 = Pb-Free: SymbolCreator: a0412235
Logo3 = CMP-0074769-1
Logo4 = CMP-0074847-1: FCC_disclaimer; Library Reference: Logo
QC1-QC4 = CMP-0037654-1: 100-V, 64-A GaN with Integrated Driver; Manufacturer: Texas Instruments; SizeZ_mm: 0.85mm; AEC Qualified: No; Max Supply Voltage: 5.25V; Min Supply Voltage: 4.75V; Nominal Supply Current: 3mA; Number Of Drivers: 1; Propagation Delay: 55ns; Standoff Height: 0mm; TJmax_C: +125°C
R1 R2 = CMP-02407-004899-1: RES Thick Film, 3.01Ω, 1%, 0.063W, 200ppm/°C, 0402; Max Power Dissipation: 63mW; Voltage Rating (DC): 50V
R3 R4 = CMP-0016888-3: RES, 2.55, 1%, 0.25 W, AEC-Q200 Grade 0, 1206; Manufacturer: Vishay-Dale; Power_W: 250mW; TempCo: 100 ppm/C; Value_Code: 2R55; Value: 2.55; EIA_Code: E96; SizeX_mm: 3.2; SizeY_mm: 1.6; SizeZ_mm: 1.35; Value2: 0.25W; SizeArea_mm2: 5.12; AEC Qualified: Y; VDC_V: 200V; AEC Category: Q200; AEC Grade: 0
R5 = CMP-0022550-4: RES, 681 k, 1%, 0.1 W, AEC-Q200 Grade 0, 0603; Manufacturer: Vishay-Dale; Power_W: 100mW; TempCo: 100 ppm/C; Value: 681k; EIA_Code: E96; SizeX_mm: 1.6; SizeY_mm: 0.8; SizeZ_mm: 1; Value2: 0.1W; SizeArea_mm2: 1.28; AEC Qualified: Y; VDC_V: 75V; AEC Category: Q200; AEC Grade: 0
R6 = CMP-0022042-4: RES, 13.0 k, 1%, 0.1 W, AEC-Q200 Grade 0, 0603; Manufacturer: Vishay-Dale; Power_W: 100mW; TempCo: 100 ppm/C; Value_Code: 13k0; Value: 13.0k; EIA_Code: E96; Res_ohm: 13k; SizeX_mm: 1.6; SizeY_mm: 0.8; SizeZ_mm: 1; Value2: 0.1W; SizeArea_mm2: 1.28; AEC Qualified: Y; VDC_V: 75V; AEC Category: Q200; AEC Grade: 0
RC1 RC2 = CMP-0018270-2: RES, 3.30, 1%, 0.25 W, 1206; Manufacturer: Yageo America; Power_W: 250mW; TempCo: 200 ppm/C; Value_Code: 3R30; U/M: EA; Value: 3.30; Res_ohm: 3.3; SizeX_mm: 3.2; SizeY_mm: 1.6; SizeZ_mm: 1.35; Value2: 0.25W; SizeArea_mm2: 5.12; VDC_V: 200V; AEC Category: Q200
RC3 RC4 = CMP-0015357-3: RES, 0.002, 2%, 1 W, 0508; Manufacturer: Susumu Co Ltd; Power_W: 1W; TempCo: 100 ppm/C; SizeAreaWB_mm2: 6.75; Value_Code: 2L000; U/M: EA; Value: 0.002; Res_ohm: 2m; SizeX_mm: 1.25; SizeY_mm: 2; SizeZ_mm: 1; SizeArea_mm2: 2.5; AEC Category: Q200
RC5 RC6 RC18 = CMP-0096818-1: 0 Ohms Jumper 0.245W Chip Resistor 0805 (2012 Metric) - Metal Element; Manufacturer: Ohmite; AEC Qualified: No; Value: 0; Power_W: 245mW; SizeZ_mm: 0.55mm
RC7 = CRCW0603270KJNEA: RES, 270 k, 5%, 0.1 W, 0603; Manufacturer: Vishay-Dale; CompType: Resistor; Value: 270k; Res_ohm: 270000; Tolerance_%: 5; Power_W: 0.1; Value2: 0.1W; VDC_V: 75; TempCo: 200 ppm/C; SizeArea_mm2: 1.28; SizeX_mm: 1.6; SizeY_mm: 0.8; SizeZ_mm: 1; EIA_Code: E24; U/M: EA; AEC Category: Q200
RC8 RC10 = RC0603FR-07100RL: RES, 100, 1%, 0.1 W, 0603; Manufacturer: Yageo America; CompType: Resistor; Value: 100; Value_Code: 100R; Tolerance_%: 1; Power_W: 0.1; Value2: 0.1W; VDC_V: 150; TempCo: 200 ppm/C; SizeArea_mm2: 1.28; SizeX_mm: 1.6; SizeY_mm: 0.8; EIA_Code: E96; U/M: EA; AEC Category: Q200; Green_Lifecycle: Active; Green_REACh: Passed
RC9 = CRCW060310K0FKEA: RES, 10.0 k, 1%, 0.1 W, 0603; Manufacturer: Vishay-Dale; CompType: Resistor; Value: 10.0k; Res_ohm: 10000; Value_Code: 10k0; Tolerance_%: 1; Power_W: 0.1; Value2: 0.1W; VDC_V: 75; TempCo: 100 ppm/C; SizeArea_mm2: 1.28; SizeX_mm: 1.6; SizeY_mm: 0.8; EIA_Code: E96; U/M: EA; AEC Category: Q200; Green_Lifecycle: Active; Green_REACh: Passed
RC11 = CRCW0603100RFKEA: RES, 100, 1%, 0.1 W, 0603; Manufacturer: Vishay-Dale; CompType: Resistor; Value: 100; Value_Code: 100R; Tolerance_%: 1; Power_W: 0.1; Value2: 0.1W; VDC_V: 75; TempCo: 100 ppm/C; SizeArea_mm2: 1.28; SizeX_mm: 1.6; SizeY_mm: 0.8; EIA_Code: E96; U/M: EA; AEC Category: Q200; Green_Lifecycle: Active; Green_REACh: Passed
RC12 = CRCW060310K7FKEA: RES, 10.7 k, 1%, 0.1 W, 0603; Manufacturer: Vishay-Dale; CompType: Resistor; Value: 10.7k; Res_ohm: 10700; Value_Code: 10k7; Tolerance_%: 1; Power_W: 0.1; Value2: 0.1W; VDC_V: 75; TempCo: 100 ppm/C; SizeArea_mm2: 1.28; SizeX_mm: 1.6; SizeY_mm: 0.8; EIA_Code: E96; U/M: EA; AEC Category: Q200; Green_Lifecycle: Active; Green_REACh: Passed
RC13 RC14 RC16 RC19 = CMP-0025697-4: RES, 0, 5%, 0.1 W, AEC-Q200 Grade 0, 0603; Manufacturer: Vishay-Dale; Power_W: 100mW; TempCo: 200 ppm/C; Value_Code: 0000; Value: 0; EIA_Code: E24; SizeX_mm: 1.6; SizeY_mm: 0.8; SizeZ_mm: 1; Value2: 0.1W; SizeArea_mm2: 1.28; AEC Qualified: Y; VDC_V: 75V; AEC Category: Q200
RC15 = CMP-0026403-2: RES, 49.9 k, 1%, 0.063 W, AEC-Q200 Grade 0, 0402; Manufacturer: Vishay-Dale; Power_W: 63mW; TempCo: 100 ppm/C; Value_Code: 49k9; Value: 49.9k; EIA_Code: E96; SizeX_mm: 1; SizeY_mm: 0.5; SizeZ_mm: 0.6; Value2: 0.063W; CompType: Resistor; AEC Qualified: Y; VDC_V: 50V; AEC Category: Q200; AEC Grade: 0
RC17 = CMP-0026728-1: RES, 220 k, 1%, 0.0625 W, 0402; Manufacturer: Yageo America; Power_W: 62.5mW; TempCo: 100 ppm/C; U/M: EA; Value: 220k; SizeX_mm: 1; SizeY_mm: 0.5; SizeZ_mm: 0.6; CompType: Resistor; AEC Qualified: N; VDC_V: 50V; AEC Category: Q200
RC20 RC21 = CMP-0078244-2: RES, 30.0 k, 1%, 0.063 W, AEC-Q200 Grade 0, 0402; Manufacturer: Vishay-Dale; Power_W: 63mW; Green_Lifecycle: Active; TempCo: 100 ppm/C; Value_Code: 30k0; Green_REACh: Passed; Value: 30.0k; Res_ohm: 30k; SizeX_mm: 1; SizeY_mm: 0.5; SizeZ_mm: 0.6; Value2: 0.063W; CompType: Resistor; AEC Qualified: Y; VDC_V: 50V; AEC Grade: 0; AEC Category: Q200
RC22 = CMP-0089989-1: 2.87 kOhms ±1% 0.1W, 1/10W Chip Resistor 0402 (1005 Metric) Automotive AEC-Q200, Moisture Resistant Thick Film; Manufacturer: KOA Speer; AEC Qualified: Yes; VDC_V: 75V; Value: 2.87k; SizeZ_mm: 0.4mm; AEC Grade: Grade 0; TempCo: 100ppm/°C; Power_W: 100mW; Standoff Height: 0mm
RC23 = CRCW06038K25FKEA: RES, 8.25 k, 1%, 0.1 W, 0603; Manufacturer: Vishay-Dale; CompType: Resistor; Value: 8.25k; Res_ohm: 8250; Value_Code: 8k25; Tolerance_%: 1; Power_W: 0.1; Value2: 0.1W; VDC_V: 75; TempCo: 100 ppm/C; SizeArea_mm2: 1.28; SizeX_mm: 1.6; SizeY_mm: 0.8; EIA_Code: E96; U/M: EA; AEC Category: Q200; Green_Lifecycle: Active; Green_REACh: Passed
RC24 = CRCW0603100KFKEA: RES, 100 k, 1%, 0.1 W, 0603; Manufacturer: Vishay-Dale; CompType: Resistor; Value: 100k; Res_ohm: 100000; Tolerance_%: 1; Power_W: 0.1; Value2: 0.1W; VDC_V: 75; TempCo: 100 ppm/C; SizeArea_mm2: 1.28; SizeX_mm: 1.6; SizeY_mm: 0.8; EIA_Code: E96; U/M: EA; AEC Category: Q200; Green_Lifecycle: Active; Green_REACh: Passed
RC25 = CMP-0022064-4: RES, 158 k, 1%, 0.1 W, AEC-Q200 Grade 0, 0603; Manufacturer: Vishay-Dale; Power_W: 100mW; TempCo: 100 ppm/C; Value: 158k; EIA_Code: E96; SizeX_mm: 1.6; SizeY_mm: 0.8; SizeZ_mm: 1; Value2: 0.1W; SizeArea_mm2: 1.28; AEC Qualified: Y; VDC_V: 75V; AEC Category: Q200; AEC Grade: 0
UC1 = CMP-0094661-2: Wide VIN Bidirectional 4 Switch Buck-Boost Controller; Manufacturer: Texas Instruments; Output Voltage: 3.3-78V; Max Supply Voltage: 78V; AEC Qualified: No; SizeZ_mm: 1.2mm; Switching Frequency: 100-2000kHz; AEC Category: Q200; Number Of Outputs: 2; Min Supply Voltage: 2.8V; Output Type: AdjustableProgrammable; Max Duty Cycle: 100%; CompType: IC; Standoff Height: 0.05mm; Nominal Supply Current: 25uA; TJmax_C: +125°C
UC2 = CMP-0097277-1: 3V to 16 V Input, 3-A Synchronous Step-Down Voltage Regulator Module, QFN-FCMOD7; Manufacturer: Texas Instruments; Nominal Supply Current: 120-400uA; SizeZ_mm: 2.1mm; AEC Qualified: No; Output Type: AdjustableProgrammable; Switching Topology: Buck; AEC Grade: NA; Standoff Height: 0mm; Max Supply Voltage: 16V; Number Of Outputs: 1; Switching Frequency: 1400/2000kHz; TJmax_C: +125°C; Max Duty Cycle: 98%; Output Voltage: 0.6-7V

## Sheet PMP41155_Power Module_1.SchDoc
size 431 x 279 mm; Date: Not shown in title block; ApprovedBy: Not shown in title block; CheckedBy: Not shown in title block; Author: Not shown in title block; CompanyName: Not shown in title block; Engineer: Not shown in title block; Organization: Not shown in title block; Address1: Not shown in title block; Address2: Not shown in title block; Address3: Not shown in title block; Address4: Not shown in title block; DocumentNumber: 1; Revision: Use project parameter SCH_Rev; SheetNumber: 2; SheetTotal: 2; PageSetup: Record=PageOptions¦CenterHorizontal=True¦CenterVertical=True¦PrintScale=1.00¦XCorrection=1.00¦YCorrection=1.00¦PrintKind=0¦BorderSize=5000000¦LeftOffset=0¦BottomOffset=0¦Orientation=2¦PaperLength=1000¦PaperWidth=1000¦Scale=100¦PaperSource=15¦PrintQuality=600¦MediaType=1¦DitherType=10¦PaperKind=Letter¦PrintScaleMode=1
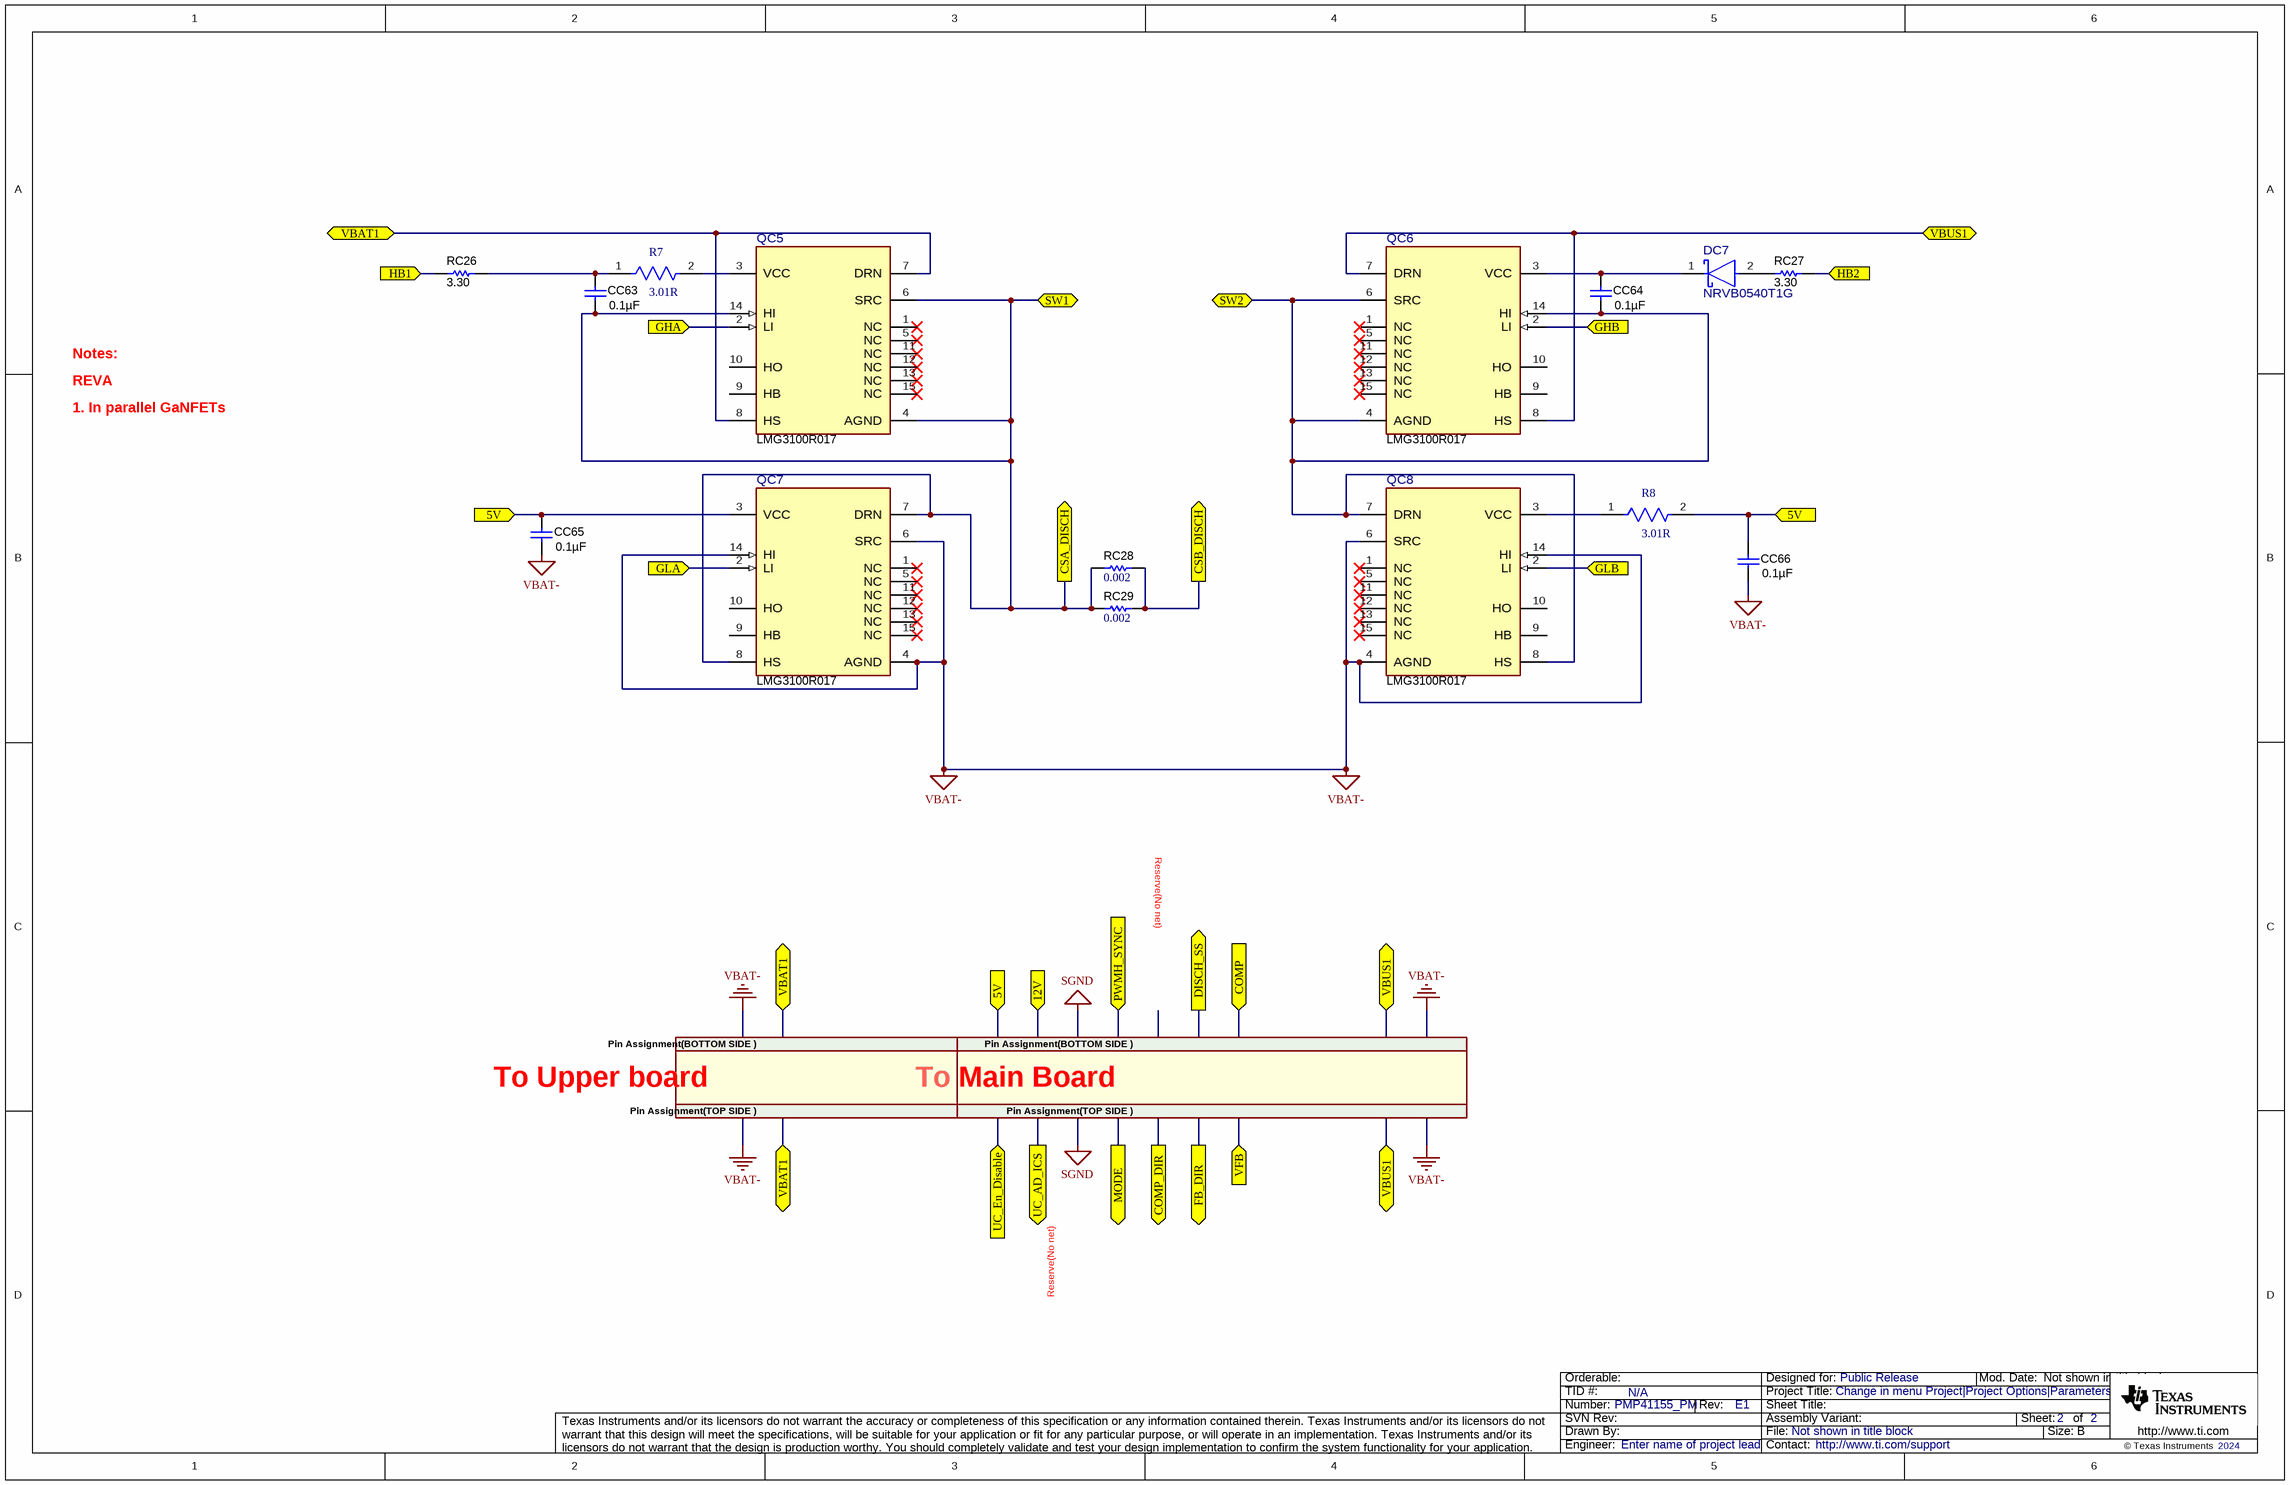
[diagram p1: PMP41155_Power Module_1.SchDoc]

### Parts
CC63  ValueDisplayed: 0.1µF  [0402]  (hidden comment: GCM155R71C104JA55D)
CC64  ValueDisplayed: 0.1µF  [0402]  (hidden comment: GCM155R71C104JA55D)
CC65  ValueDisplayed: 0.1µF  [0402]  (hidden comment: GCM155R71C104JA55D)
CC66  ValueDisplayed: 0.1µF  [0402]  (hidden comment: GCM155R71C104JA55D)
DC7  NRVB0540T1G  [FP-NRVB0540T1G_SOD-123-MFG]
QC5  LMG3100R017  [VBE0015A-MFG]
QC6  LMG3100R017  [VBE0015A-MFG]
QC7  LMG3100R017  [VBE0015A-MFG]
QC8  LMG3100R017  [VBE0015A-MFG]
R7  Resistance: 3.01R  [FP-CRCW0402-e3-MFG]  (hidden comment: CRCW04023R01FNED)
R8  Resistance: 3.01R  [FP-CRCW0402-e3-MFG]  (hidden comment: CRCW04023R01FNED)
RC26  ValueDisplayed: 3.30  [1206]  (hidden comment: RC1206FR-073R3L)
RC27  ValueDisplayed: 3.30  [1206]  (hidden comment: RC1206FR-073R3L)
RC28  ValueDisplayed: 0.002  [0508]  (hidden comment: KRL2012E-M-R002-G-T5)
RC29  ValueDisplayed: 0.002  [0508]  (hidden comment: KRL2012E-M-R002-G-T5)

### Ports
5V (in), 12V (in), COMP (in), COMP_DIR (out), CSA_DISCH (out), CSB_DISCH (out), DISCH_SS (out), FB_DIR (out), GHA (in), GHB (in), GLA (in), GLB (in), HB1 (in), HB2 (in), MODE (out), PWMH_SYNC (in), SW1 (bidir), SW2 (bidir), UC_AD_ICS (out), UC_En_Disable (in), VBAT1 (bidir), VBUS1 (bidir), VFB (in)

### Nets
SGND: CC65.2 CC66.2 QC7.4(AGND) QC7.6(SRC) QC7.14(HI) QC8.4(AGND) QC8.6(SRC) QC8.14(HI)  [also labelled VBAT-]
5V: CC65.1 CC66.1 QC7.3(VCC) R8.2 ; port 5V
CSA_DISCH: CC63.2 QC5.4(AGND) QC5.6(SRC) QC5.14(HI) QC7.7(DRN) QC7.8(HS) RC28.1 RC29.1 ; port SW1, port CSA_DISCH
CSB_DISCH: RC28.2 RC29.2 ; port CSB_DISCH
GHA: QC5.2(LI) ; port GHA
GHB: QC6.2(LI) ; port GHB
GLA: QC7.2(LI) ; port GLA
GLB: QC8.2(LI) ; port GLB
HB1: RC26.1 ; port HB1
HB2: RC27.2 ; port HB2
SW2: CC64.2 QC6.4(AGND) QC6.6(SRC) QC6.14(HI) QC8.7(DRN) QC8.8(HS) ; port SW2
VBAT1: QC5.7(DRN) QC5.8(HS) ; port VBAT1
VBUS1: QC6.7(DRN) QC6.8(HS) ; port VBUS1
NetCC63_1: CC63.1 R7.1 RC26.2
NetCC64_1: CC64.1 DC7.1(CATHODE) QC6.3(VCC)
NetDC7_2: DC7.2(ANODE) RC27.1
NetQC5_3: QC5.3(VCC) R7.2
NetQC8_3: QC8.3(VCC) R8.1

Not connected (* = marked no-connect by the designer): QC5 1(NC)* 5(NC)* 9(HB) 10(HO) 11(NC)* 12(NC)* 13(NC)* 15(NC)*; QC6 1(NC)* 5(NC)* 9(HB) 10(HO) 11(NC)* 12(NC)* 13(NC)* 15(NC)*; QC7 1(NC)* 5(NC)* 9(HB) 10(HO) 11(NC)* 12(NC)* 13(NC)* 15(NC)*; QC8 1(NC)* 5(NC)* 9(HB) 10(HO) 11(NC)* 12(NC)* 13(NC)* 15(NC)*

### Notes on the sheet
- Notes:
- 1. In parallel GaNFETs
- REVA
- Reserve(No net)
- To Upper board
- Pin Assignment(BOTTOM SIDE )
- Pin Assignment(TOP SIDE )
- To Main Board

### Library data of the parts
CC63-CC66 = CMP-0080702-1: as CC28 on sheet PMP41155_Power Module
DC7 = CMP-0090564-1: as DC1 on sheet PMP41155_Power Module
QC5-QC8 = CMP-0037654-1: as QC1 on sheet PMP41155_Power Module
R7 R8 = CMP-02407-004899-1: as R1 on sheet PMP41155_Power Module
RC26 RC27 = CMP-0018270-2: as RC1 on sheet PMP41155_Power Module
RC28 RC29 = CMP-0015357-3: as RC3 on sheet PMP41155_Power Module

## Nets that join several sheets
SGND: PMP41155_Power Module (89 pins), PMP41155_Power Module_1 (8 pins)
5V: PMP41155_Power Module (8 pins), PMP41155_Power Module_1 (CC65.1 CC66.1 QC7.3 R8.2)
CSA_DISCH: PMP41155_Power Module (14 pins), PMP41155_Power Module_1 (8 pins)
CSB_DISCH: PMP41155_Power Module (LC1.1 RC3.2 RC4.2 RC10.2), PMP41155_Power Module_1 (RC28.2 RC29.2)
GHA: PMP41155_Power Module (QC1.2 RC13.2), PMP41155_Power Module_1 (QC5.2)
GHB: PMP41155_Power Module (QC2.2 RC16.2), PMP41155_Power Module_1 (QC6.2)
GLA: PMP41155_Power Module (QC3.2 RC14.2), PMP41155_Power Module_1 (QC7.2)
GLB: PMP41155_Power Module (QC4.2 RC19.2), PMP41155_Power Module_1 (QC8.2)
HB1: PMP41155_Power Module (CC53.2 DC5.1 RC1.1 UC1.35), PMP41155_Power Module_1 (RC26.1)
HB2: PMP41155_Power Module (CC54.2 DC6.1 RC2.2 UC1.26), PMP41155_Power Module_1 (RC27.2)
SW2: PMP41155_Power Module (16 pins), PMP41155_Power Module_1 (6 pins)
VBAT1: PMP41155_Power Module (25 pins), PMP41155_Power Module_1 (QC5.7 QC5.8)
VBUS1: PMP41155_Power Module (24 pins), PMP41155_Power Module_1 (QC6.7 QC6.8)

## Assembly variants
001: all parts fitted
